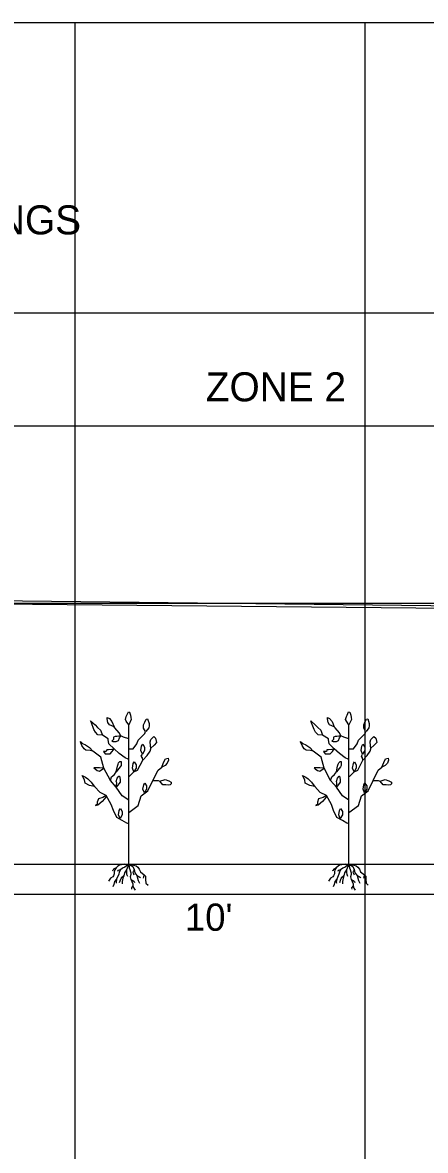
# Model space of a CAD drawing. Extents: x 1578769 to 1579225, y 724002 to 724828.
# Drawn here: x 1578849.13 to 1578856.07, y 724397.74 to 724417.15 of the extents above; entities that cross this region are included whole.
import ezdxf

# ---------------------------------------------------------------- set-up
doc = ezdxf.new("R2010")
doc.units = 0
for name, color, linetype in [('1', 7, 'Continuous'), ('Default', 7, 'Continuous'), ('Old_Level_1', 7, 'Continuous'), ('Old_Level_41', 7, 'Continuous'), ('R_Exist Surface', 7, 'Continuous'), ('R_Fin Surface', 7, 'Continuous')]:
    doc.layers.add(name, color=color, linetype=linetype)

msp = doc.modelspace()

# ---------------------------------------------------------------- linework, layer by layer
at = {"layer": '1'}
for p, q in [((1578848.492, 724410.203), (1578858.497, 724410.203)), ((1578850.961, 724402.662), (1578850.961, 724405.062)), ((1578854.751, 724402.662), (1578854.751, 724405.062)), ((1578850.966, 724402.657), (1578850.968, 724402.661)), ((1578854.756, 724402.657), (1578854.758, 724402.661))]:
    msp.add_line(p, q, dxfattribs=at)
for points in [[(1578850.961, 724405.062), (1578850.917, 724405.125), (1578850.905, 724405.15), (1578850.917, 724405.201), (1578850.93, 724405.226), (1578850.955, 724405.283), (1578850.974, 724405.276), (1578850.993, 724405.226), (1578850.999, 724405.188), (1578851.005, 724405.15)], [(1578854.751, 724405.062), (1578854.707, 724405.125), (1578854.694, 724405.15), (1578854.707, 724405.201), (1578854.72, 724405.226), (1578854.745, 724405.283), (1578854.764, 724405.276), (1578854.783, 724405.226), (1578854.789, 724405.188), (1578854.795, 724405.15)], [(1578850.507, 724404.885), (1578850.431, 724404.891), (1578850.387, 724404.935), (1578850.362, 724404.98), (1578850.318, 724405.093), (1578850.305, 724405.131), (1578850.381, 724405.062), (1578850.425, 724405.017), (1578850.475, 724404.967)], [(1578850.709, 724405.024), (1578850.627, 724405.062), (1578850.602, 724405.1), (1578850.589, 724405.163), (1578850.589, 724405.188), (1578850.627, 724405.169), (1578850.671, 724405.119)], [(1578854.297, 724404.885), (1578854.221, 724404.891), (1578854.177, 724404.935), (1578854.152, 724404.98), (1578854.107, 724405.093), (1578854.095, 724405.131), (1578854.171, 724405.062), (1578854.215, 724405.017), (1578854.265, 724404.967)], [(1578854.499, 724405.024), (1578854.417, 724405.062), (1578854.391, 724405.1), (1578854.379, 724405.163), (1578854.379, 724405.188), (1578854.417, 724405.169), (1578854.461, 724405.119)], [(1578850.822, 724404.872), (1578850.754, 724404.858), (1578850.725, 724404.858), (1578850.697, 724404.848), (1578850.697, 724404.81), (1578850.668, 724404.781), (1578850.687, 724404.772), (1578850.744, 724404.772), (1578850.783, 724404.791), (1578850.802, 724404.838)], [(1578854.612, 724404.872), (1578854.544, 724404.858), (1578854.515, 724404.858), (1578854.486, 724404.848), (1578854.486, 724404.81), (1578854.458, 724404.781), (1578854.477, 724404.772), (1578854.534, 724404.772), (1578854.572, 724404.791), (1578854.591, 724404.838)], [(1578850.709, 724404.645), (1578850.668, 724404.638), (1578850.611, 724404.628), (1578850.582, 724404.628), (1578850.572, 724404.6), (1578850.525, 724404.6), (1578850.553, 724404.561), (1578850.592, 724404.561), (1578850.639, 724404.561), (1578850.677, 724404.6)], [(1578854.499, 724404.645), (1578854.458, 724404.638), (1578854.401, 724404.628), (1578854.372, 724404.628), (1578854.362, 724404.6), (1578854.315, 724404.6), (1578854.343, 724404.561), (1578854.381, 724404.561), (1578854.429, 724404.561), (1578854.467, 724404.6)], [(1578850.747, 724404.253), (1578850.766, 724404.348), (1578850.778, 724404.386), (1578850.785, 724404.405), (1578850.81, 724404.43), (1578850.829, 724404.43), (1578850.829, 724404.361), (1578850.816, 724404.335)], [(1578854.537, 724404.253), (1578854.555, 724404.348), (1578854.568, 724404.386), (1578854.574, 724404.405), (1578854.6, 724404.43), (1578854.619, 724404.43), (1578854.619, 724404.361), (1578854.606, 724404.335)], [(1578850.372, 724403.998), (1578850.286, 724404.017), (1578850.21, 724404.055), (1578850.2, 724404.112), (1578850.162, 724404.189), (1578850.219, 724404.16), (1578850.257, 724404.131), (1578850.315, 724404.074), (1578850.343, 724404.036)], [(1578850.747, 724403.988), (1578850.754, 724404.065), (1578850.744, 724404.084), (1578850.763, 724404.141), (1578850.792, 724404.179), (1578850.802, 724404.179), (1578850.811, 724404.122), (1578850.811, 724404.074)], [(1578854.162, 724403.998), (1578854.076, 724404.017), (1578854, 724404.055), (1578853.99, 724404.112), (1578853.952, 724404.189), (1578854.009, 724404.16), (1578854.047, 724404.131), (1578854.105, 724404.074), (1578854.133, 724404.036)], [(1578854.537, 724403.988), (1578854.544, 724404.065), (1578854.534, 724404.084), (1578854.553, 724404.141), (1578854.582, 724404.179), (1578854.591, 724404.179), (1578854.601, 724404.122), (1578854.601, 724404.074)], [(1578850.572, 724403.845), (1578850.515, 724403.807), (1578850.439, 724403.788), (1578850.42, 724403.73), (1578850.42, 724403.692), (1578850.391, 724403.673), (1578850.429, 724403.682), (1578850.506, 724403.749), (1578850.515, 724403.749), (1578850.572, 724403.816)], [(1578854.362, 724403.845), (1578854.305, 724403.807), (1578854.229, 724403.788), (1578854.21, 724403.73), (1578854.21, 724403.692), (1578854.181, 724403.673), (1578854.219, 724403.682), (1578854.296, 724403.749), (1578854.305, 724403.749), (1578854.362, 724403.816)]]:
    msp.add_lwpolyline(points, close=True, dxfattribs=at)
for points in [[(1578851.248, 724404.948), (1578851.217, 724405.005), (1578851.217, 724405.062), (1578851.236, 724405.106), (1578851.261, 724405.156), (1578851.286, 724405.163), (1578851.312, 724405.081), (1578851.312, 724405.043), (1578851.305, 724405.011), (1578851.255, 724404.948)], [(1578855.038, 724404.948), (1578855.007, 724405.005), (1578855.007, 724405.062), (1578855.026, 724405.106), (1578855.051, 724405.156), (1578855.076, 724405.163), (1578855.101, 724405.081), (1578855.101, 724405.043), (1578855.095, 724405.011), (1578855.045, 724404.948)], [(1578850.949, 724404.468), (1578850.898, 724404.493), (1578850.797, 724404.569), (1578850.709, 724404.645), (1578850.62, 724404.733), (1578850.608, 724404.809), (1578850.608, 724404.822), (1578850.507, 724404.885)], [(1578850.961, 724404.822), (1578850.873, 724404.847), (1578850.822, 724404.872), (1578850.797, 724404.923), (1578850.721, 724405.011), (1578850.709, 724405.024)], [(1578850.961, 724404.645), (1578851.037, 724404.645), (1578851.1, 724404.733), (1578851.125, 724404.796), (1578851.239, 724404.91), (1578851.252, 724404.948)], [(1578854.739, 724404.468), (1578854.688, 724404.493), (1578854.587, 724404.569), (1578854.499, 724404.645), (1578854.41, 724404.733), (1578854.398, 724404.809), (1578854.398, 724404.822), (1578854.297, 724404.885)], [(1578854.751, 724404.822), (1578854.663, 724404.847), (1578854.612, 724404.872), (1578854.587, 724404.923), (1578854.511, 724405.011), (1578854.499, 724405.024)], [(1578854.751, 724404.645), (1578854.827, 724404.645), (1578854.89, 724404.733), (1578854.915, 724404.796), (1578855.029, 724404.91), (1578855.041, 724404.948)], [(1578850.343, 724404.607), (1578850.299, 724404.62), (1578850.223, 724404.626), (1578850.191, 724404.645), (1578850.154, 724404.702), (1578850.128, 724404.765), (1578850.128, 724404.771), (1578850.166, 724404.74), (1578850.217, 724404.714), (1578850.286, 724404.67), (1578850.343, 724404.607)], [(1578851.195, 724404.556), (1578851.17, 724404.62), (1578851.182, 724404.695), (1578851.201, 724404.727), (1578851.233, 724404.676), (1578851.233, 724404.62), (1578851.195, 724404.556)], [(1578851.34, 724404.645), (1578851.327, 724404.765), (1578851.34, 724404.809), (1578851.39, 724404.86), (1578851.422, 724404.828), (1578851.441, 724404.759), (1578851.397, 724404.708), (1578851.34, 724404.657)], [(1578854.133, 724404.607), (1578854.089, 724404.62), (1578854.013, 724404.626), (1578853.981, 724404.645), (1578853.943, 724404.702), (1578853.918, 724404.765), (1578853.918, 724404.771), (1578853.956, 724404.74), (1578854.006, 724404.714), (1578854.076, 724404.67), (1578854.133, 724404.607)], [(1578854.985, 724404.556), (1578854.959, 724404.62), (1578854.972, 724404.695), (1578854.991, 724404.727), (1578855.023, 724404.676), (1578855.023, 724404.62), (1578854.985, 724404.556)], [(1578855.13, 724404.645), (1578855.117, 724404.765), (1578855.13, 724404.809), (1578855.18, 724404.86), (1578855.212, 724404.828), (1578855.231, 724404.759), (1578855.187, 724404.708), (1578855.13, 724404.657)], [(1578850.961, 724403.761), (1578850.848, 724403.836), (1578850.747, 724403.988), (1578850.646, 724404.102), (1578850.532, 724404.316), (1578850.482, 724404.506), (1578850.343, 724404.607)], [(1578850.961, 724404.177), (1578850.974, 724404.177), (1578851.05, 724404.253), (1578851.113, 724404.279), (1578851.201, 724404.455), (1578851.277, 724404.531), (1578851.327, 724404.607), (1578851.34, 724404.645)], [(1578851.201, 724404.455), (1578851.195, 724404.493), (1578851.176, 724404.519), (1578851.195, 724404.556)], [(1578851.529, 724404.329), (1578851.561, 724404.411), (1578851.592, 724404.474), (1578851.637, 724404.487), (1578851.643, 724404.455), (1578851.624, 724404.399), (1578851.586, 724404.361), (1578851.529, 724404.329)], [(1578854.751, 724403.761), (1578854.638, 724403.836), (1578854.537, 724403.988), (1578854.436, 724404.102), (1578854.322, 724404.316), (1578854.271, 724404.506), (1578854.133, 724404.607)], [(1578854.751, 724404.177), (1578854.764, 724404.177), (1578854.839, 724404.253), (1578854.903, 724404.279), (1578854.991, 724404.455), (1578855.067, 724404.531), (1578855.117, 724404.607), (1578855.13, 724404.645)], [(1578854.991, 724404.455), (1578854.985, 724404.493), (1578854.966, 724404.519), (1578854.985, 724404.556)], [(1578855.319, 724404.329), (1578855.351, 724404.411), (1578855.382, 724404.474), (1578855.426, 724404.487), (1578855.433, 724404.455), (1578855.414, 724404.399), (1578855.376, 724404.361), (1578855.319, 724404.329)], [(1578850.532, 724404.316), (1578850.458, 724404.323), (1578850.401, 724404.323), (1578850.362, 724404.323), (1578850.382, 724404.303), (1578850.42, 724404.275), (1578850.458, 724404.265), (1578850.534, 724404.313)], [(1578850.961, 724403.553), (1578851.125, 724403.672), (1578851.176, 724403.836), (1578851.289, 724403.925), (1578851.378, 724404.102), (1578851.466, 724404.279), (1578851.529, 724404.329)], [(1578851.05, 724404.253), (1578851.024, 724404.316), (1578851.037, 724404.392), (1578851.056, 724404.424), (1578851.088, 724404.373), (1578851.088, 724404.316), (1578851.05, 724404.253)], [(1578854.322, 724404.316), (1578854.248, 724404.323), (1578854.19, 724404.323), (1578854.152, 724404.323), (1578854.171, 724404.303), (1578854.21, 724404.275), (1578854.248, 724404.265), (1578854.324, 724404.313)], [(1578854.751, 724403.553), (1578854.915, 724403.672), (1578854.966, 724403.836), (1578855.079, 724403.925), (1578855.168, 724404.102), (1578855.256, 724404.279), (1578855.319, 724404.329)], [(1578854.839, 724404.253), (1578854.814, 724404.316), (1578854.827, 724404.392), (1578854.846, 724404.424), (1578854.877, 724404.373), (1578854.877, 724404.316), (1578854.839, 724404.253)], [(1578850.646, 724404.102), (1578850.665, 724404.165), (1578850.715, 724404.203), (1578850.747, 724404.253)], [(1578851.378, 724404.102), (1578851.441, 724404.102), (1578851.466, 724404.102), (1578851.498, 724404.089)], [(1578851.498, 724404.089), (1578851.586, 724404.121), (1578851.649, 724404.095), (1578851.693, 724404.076), (1578851.693, 724404.045), (1578851.674, 724404.026), (1578851.643, 724404.02), (1578851.599, 724404.026), (1578851.548, 724404.026), (1578851.498, 724404.089)], [(1578854.436, 724404.102), (1578854.455, 724404.165), (1578854.505, 724404.203), (1578854.537, 724404.253)], [(1578855.168, 724404.102), (1578855.231, 724404.102), (1578855.256, 724404.102), (1578855.288, 724404.089)], [(1578855.288, 724404.089), (1578855.376, 724404.121), (1578855.439, 724404.095), (1578855.483, 724404.076), (1578855.483, 724404.045), (1578855.464, 724404.026), (1578855.433, 724404.02), (1578855.389, 724404.026), (1578855.338, 724404.026), (1578855.288, 724404.089)], [(1578850.964, 724403.358), (1578850.926, 724403.367), (1578850.849, 724403.415), (1578850.754, 724403.463), (1578850.697, 724403.587), (1578850.658, 724403.692), (1578850.572, 724403.845), (1578850.467, 724403.893), (1578850.372, 724403.998), (1578850.372, 724403.998)], [(1578851.231, 724403.888), (1578851.205, 724403.951), (1578851.218, 724404.027), (1578851.237, 724404.058), (1578851.268, 724404.008), (1578851.268, 724403.951), (1578851.231, 724403.888)], [(1578854.754, 724403.358), (1578854.716, 724403.367), (1578854.639, 724403.415), (1578854.544, 724403.463), (1578854.486, 724403.587), (1578854.448, 724403.692), (1578854.362, 724403.845), (1578854.257, 724403.893), (1578854.162, 724403.998), (1578854.162, 724403.998)], [(1578855.02, 724403.888), (1578854.995, 724403.951), (1578855.008, 724404.027), (1578855.027, 724404.058), (1578855.058, 724404.008), (1578855.058, 724403.951), (1578855.02, 724403.888)], [(1578850.811, 724403.448), (1578850.785, 724403.511), (1578850.798, 724403.587), (1578850.817, 724403.619), (1578850.848, 724403.568), (1578850.848, 724403.511), (1578850.811, 724403.448)], [(1578854.6, 724403.448), (1578854.575, 724403.511), (1578854.588, 724403.587), (1578854.607, 724403.619), (1578854.638, 724403.568), (1578854.638, 724403.511), (1578854.6, 724403.448)], [(1578850.961, 724402.662), (1578850.91, 724402.656), (1578850.894, 724402.66), (1578850.836, 724402.652), (1578850.801, 724402.644), (1578850.774, 724402.629), (1578850.743, 724402.598), (1578850.72, 724402.563), (1578850.712, 724402.528), (1578850.712, 724402.497), (1578850.697, 724402.462), (1578850.685, 724402.446), (1578850.646, 724402.419), (1578850.611, 724402.372)], [(1578850.743, 724402.598), (1578850.7, 724402.578), (1578850.685, 724402.555), (1578850.673, 724402.547)], [(1578850.961, 724402.662), (1578850.894, 724402.613), (1578850.856, 724402.594), (1578850.817, 724402.563), (1578850.797, 724402.524), (1578850.79, 724402.493), (1578850.751, 724402.407), (1578850.716, 724402.365), (1578850.704, 724402.314), (1578850.689, 724402.272)], [(1578850.817, 724402.563), (1578850.774, 724402.555), (1578850.77, 724402.539)], [(1578850.961, 724402.662), (1578850.921, 724402.567), (1578850.887, 724402.512), (1578850.875, 724402.462), (1578850.859, 724402.423), (1578850.848, 724402.365), (1578850.848, 724402.326)], [(1578850.921, 724402.567), (1578850.921, 724402.512), (1578850.925, 724402.489), (1578850.937, 724402.458)], [(1578850.961, 724402.662), (1578851.045, 724402.646), (1578851.088, 724402.633), (1578851.115, 724402.613), (1578851.143, 724402.574), (1578851.162, 724402.528), (1578851.228, 724402.481), (1578851.251, 724402.454), (1578851.251, 724402.396), (1578851.255, 724402.338), (1578851.294, 724402.299)], [(1578850.961, 724402.662), (1578851.03, 724402.625), (1578851.053, 724402.57), (1578851.065, 724402.516), (1578851.1, 724402.47), (1578851.123, 724402.384), (1578851.147, 724402.334)], [(1578850.961, 724402.662), (1578850.968, 724402.598), (1578850.98, 724402.57), (1578850.991, 724402.532), (1578850.999, 724402.516), (1578850.999, 724402.485), (1578850.987, 724402.446), (1578850.999, 724402.4), (1578851.015, 724402.365), (1578851.034, 724402.326), (1578851.034, 724402.291), (1578851.046, 724402.248), (1578851.069, 724402.213)], [(1578851.053, 724402.57), (1578851.042, 724402.539), (1578851.03, 724402.524), (1578851.05, 724402.477)], [(1578854.751, 724402.662), (1578854.7, 724402.656), (1578854.684, 724402.66), (1578854.626, 724402.652), (1578854.591, 724402.644), (1578854.564, 724402.629), (1578854.533, 724402.598), (1578854.51, 724402.563), (1578854.502, 724402.528), (1578854.502, 724402.497), (1578854.486, 724402.462), (1578854.475, 724402.446), (1578854.436, 724402.419), (1578854.401, 724402.372)], [(1578854.533, 724402.598), (1578854.49, 724402.578), (1578854.475, 724402.555), (1578854.463, 724402.547)], [(1578854.751, 724402.662), (1578854.684, 724402.613), (1578854.645, 724402.594), (1578854.607, 724402.563), (1578854.587, 724402.524), (1578854.579, 724402.493), (1578854.541, 724402.407), (1578854.506, 724402.365), (1578854.494, 724402.314), (1578854.479, 724402.272)], [(1578854.607, 724402.563), (1578854.564, 724402.555), (1578854.56, 724402.539)], [(1578854.751, 724402.662), (1578854.711, 724402.567), (1578854.676, 724402.512), (1578854.665, 724402.462), (1578854.649, 724402.423), (1578854.638, 724402.365), (1578854.638, 724402.326)], [(1578854.711, 724402.567), (1578854.711, 724402.512), (1578854.715, 724402.489), (1578854.727, 724402.458)], [(1578854.751, 724402.662), (1578854.835, 724402.646), (1578854.878, 724402.633), (1578854.905, 724402.613), (1578854.932, 724402.574), (1578854.952, 724402.528), (1578855.018, 724402.481), (1578855.041, 724402.454), (1578855.041, 724402.396), (1578855.045, 724402.338), (1578855.084, 724402.299)], [(1578854.751, 724402.662), (1578854.82, 724402.625), (1578854.843, 724402.57), (1578854.855, 724402.516), (1578854.89, 724402.47), (1578854.913, 724402.384), (1578854.936, 724402.334)], [(1578854.751, 724402.662), (1578854.758, 724402.598), (1578854.77, 724402.57), (1578854.781, 724402.532), (1578854.789, 724402.516), (1578854.789, 724402.485), (1578854.777, 724402.446), (1578854.789, 724402.4), (1578854.804, 724402.365), (1578854.824, 724402.326), (1578854.824, 724402.291), (1578854.835, 724402.248), (1578854.859, 724402.213)], [(1578854.843, 724402.57), (1578854.832, 724402.539), (1578854.82, 724402.524), (1578854.839, 724402.477)], [(1578850.751, 724402.407), (1578850.743, 724402.353), (1578850.747, 724402.338)], [(1578850.875, 724402.462), (1578850.828, 724402.423), (1578850.825, 724402.404), (1578850.817, 724402.4), (1578850.797, 724402.341)], [(1578850.999, 724402.4), (1578851.034, 724402.384), (1578851.057, 724402.365), (1578851.061, 724402.349)], [(1578851.1, 724402.47), (1578851.135, 724402.45), (1578851.154, 724402.438), (1578851.166, 724402.427)], [(1578851.228, 724402.481), (1578851.216, 724402.442), (1578851.212, 724402.423)], [(1578854.541, 724402.407), (1578854.533, 724402.353), (1578854.537, 724402.338)], [(1578854.665, 724402.462), (1578854.618, 724402.423), (1578854.614, 724402.404), (1578854.607, 724402.4), (1578854.587, 724402.341)], [(1578854.789, 724402.4), (1578854.824, 724402.384), (1578854.847, 724402.365), (1578854.851, 724402.349)], [(1578854.89, 724402.47), (1578854.925, 724402.45), (1578854.944, 724402.438), (1578854.956, 724402.427)], [(1578855.018, 724402.481), (1578855.006, 724402.442), (1578855.002, 724402.423)], [(1578851.034, 724402.291), (1578851.007, 724402.256), (1578851.011, 724402.233)], [(1578854.824, 724402.291), (1578854.797, 724402.256), (1578854.801, 724402.233)]]:
    msp.add_lwpolyline(points, dxfattribs=at)
at = {"layer": 'Default'}
msp.add_lwpolyline([(1578840.032, 724407.278), (1578843.972, 724407.183), (1578868.722, 724406.957), (1578870.692, 724406.938), (1578871.022, 724406.546), (1578881.302, 724394.253), (1578887.042, 724393.796), (1578904.532, 724392.22), (1578918.752, 724390.976), (1578924.862, 724390.388), (1578951.062, 724393.135), (1578979.152, 724396.133), (1578991.892, 724397.482), (1578996.872, 724398.009), (1579008.382, 724399.253), (1579066.252, 724403.439), (1579074.562, 724404.146)], dxfattribs=at)
at = {"layer": 'Old_Level_1'}
msp.add_lwpolyline([(1578820.032, 724417.146), (1578940.032, 724417.146), (1578940.032, 724387.146), (1578820.032, 724387.146)], dxfattribs=at)
at = {"layer": 'Old_Level_41'}
for p, q in [((1578850.032, 724417.146), (1578850.032, 724387.146)), ((1578855.032, 724387.146), (1578855.032, 724417.146))]:
    msp.add_line(p, q, dxfattribs=at)
for points in [[(1578940.032, 724412.146), (1578820.032, 724412.146)], [(1578940.032, 724407.146), (1578820.032, 724407.146)], [(1578820.032, 724402.146), (1578940.032, 724402.146)]]:
    msp.add_lwpolyline(points, dxfattribs=at)
at = {"layer": 'R_Exist Surface'}
msp.add_lwpolyline([(1578820.032, 724407.308), (1578840.086, 724407.296), (1578856.158, 724407.113), (1578866.051, 724406.984), (1578870.101, 724406.953), (1578871.119, 724406.484), (1578874.093, 724402.856), (1578881.072, 724394.627), (1578882.067, 724394.215), (1578883.085, 724394.135), (1578888.061, 724393.7), (1578893.092, 724393.289), (1578898.075, 724392.849), (1578907.062, 724392.008), (1578915.073, 724391.301), (1578925.131, 724390.401), (1578931.075, 724391.042), (1578938.041, 724391.763), (1578940.032, 724391.965)], dxfattribs=at)
at = {"layer": 'R_Fin Surface'}
msp.add_line((1578848.492, 724402.662), (1578858.492, 724402.662), dxfattribs=at)
msp.add_line((1578848.492, 724402.662), (1578858.492, 724402.662), dxfattribs=at)

# ---------------------------------------------------------------- texts
at = {"layer": '1'}
for s, height, p in [('TRANSPLANT OR BARE ROOT SEEDLINGS', 0.5, (1578836.394, 724413.5)), ('ZONE 2', 0.5, (1578852.287, 724410.627)), ("10'", 0.4687, (1578851.929, 724401.516))]:
    msp.add_text(s, height=height, dxfattribs=at).set_placement(p)

doc.saveas('drawing.dxf')
